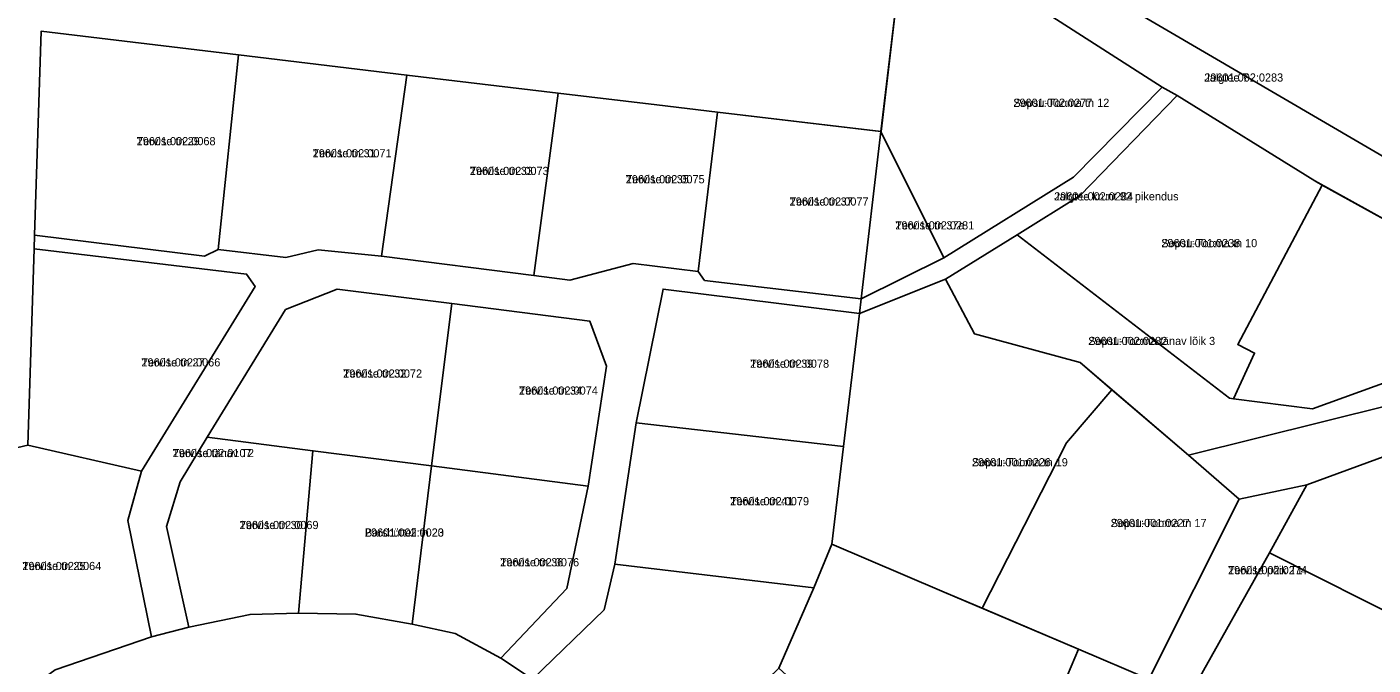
# Model space of a CAD drawing. Extents: x 518839 to 525192, y 6573164 to 6576561.
# Drawn here: x 522397.5 to 522644.9, y 6574846 to 6574963.2 of the extents above; entities that cross this region are included whole.
import ezdxf

# ---------------------------------------------------------------- set-up
doc = ezdxf.new("R2010")
doc.units = 0
for name, color, linetype in [('L_AADRESS', 7, 'Continuous'), ('PIIR', 7, 'Continuous'), ('TUNNUS', 7, 'Continuous')]:
    doc.layers.add(name, color=color, linetype=linetype)

msp = doc.modelspace()

# ---------------------------------------------------------------- linework, layer by layer
at = {"layer": 'PIIR'}
for points in [[(522594.13, 6575277.81), (522653.18, 6575274.63), (522643.43, 6575222.37), (522704.46, 6575214.76), (522708.49, 6575264.65), (522749.68, 6575255.25), (522741.36, 6575209.99), (522734.5, 6575171.21), (522773.81, 6575162.85), (522725.33, 6574926.11), (522705.01, 6574921.1), (522686, 6574922.8), (522656.89, 6574933.47), (522592.43, 6574971.18), (522560.6, 6574995.36)], [(522560.6, 6574995.36), (522592.43, 6574971.18), (522656.89, 6574933.47), (522686, 6574922.8), (522705.01, 6574921.1), (522725.33, 6574926.11), (522723.6, 6574917.68), (522697.29, 6574913.83), (522683.37, 6574910.97), (522682.62, 6574914.53), (522657.66, 6574921.95), (522634.19, 6574934.9), (522608.9, 6574950.59), (522606.14, 6574952.12), (522569.54, 6574975.64), (522558.33, 6574976.27)], [(522558.33, 6574976.27), (522569.54, 6574975.64), (522606.14, 6574952.12), (522589.83, 6574935.6), (522566.01, 6574920.76), (522554.47, 6574943.99)], [(522400.15, 6574962.4), (522436.45, 6574958.07), (522432.71, 6574922.32), (522430.18, 6574921.11), (522398.94, 6574924.94)], [(522436.45, 6574958.07), (522467.36, 6574954.37), (522462.67, 6574921.06), (522451.07, 6574922.28), (522445.13, 6574920.86), (522432.71, 6574922.32)], [(522467.36, 6574954.37), (522495.14, 6574951.05), (522490.71, 6574917.51), (522462.67, 6574921.06)], [(522495.14, 6574951.05), (522513.31, 6574948.88), (522524.42, 6574947.56), (522520.89, 6574918.25), (522508.96, 6574919.74), (522497.28, 6574916.68), (522490.71, 6574917.51)], [(522550.82, 6574913.25), (522566.01, 6574920.76), (522589.83, 6574935.6), (522606.14, 6574952.12), (522608.9, 6574950.59), (522591.05, 6574932.24), (522579.51, 6574925), (522566.31, 6574916.86), (522550.5, 6574910.54)], [(522618.51, 6574895.01), (522579.51, 6574925), (522591.05, 6574932.24), (522608.9, 6574950.59), (522634.19, 6574934.9), (522635.56, 6574934.11), (522620.02, 6574904.85), (522623.11, 6574903.27), (522619.24, 6574894.9)], [(522524.42, 6574947.56), (522554.47, 6574943.99), (522550.82, 6574913.25), (522522.07, 6574916.6), (522520.89, 6574918.25)], [(522554.47, 6574943.99), (522566.01, 6574920.76), (522550.82, 6574913.25)], [(522620.02, 6574904.85), (522635.56, 6574934.11), (522657.66, 6574921.95), (522682.62, 6574914.53), (522683.37, 6574910.97), (522633.75, 6574893.05), (522619.24, 6574894.9), (522623.11, 6574903.27)], [(522398.94, 6574924.94), (522430.18, 6574921.11), (522432.71, 6574922.32), (522445.13, 6574920.86), (522451.07, 6574922.28), (522462.67, 6574921.06), (522490.71, 6574917.51), (522497.28, 6574916.68), (522508.96, 6574919.74), (522520.89, 6574918.25), (522522.07, 6574916.6), (522550.82, 6574913.25), (522550.5, 6574910.54), (522514.43, 6574915.03), (522509.51, 6574890.48), (522505.54, 6574864.52), (522503.58, 6574856.12), (522490.42, 6574843.39), (522484.64, 6574847.21), (522496.74, 6574860.01), (522500.65, 6574878.85), (522504.03, 6574900.88), (522500.98, 6574909.12), (522475.61, 6574912.42), (522454.55, 6574915.02), (522445.07, 6574911.26), (522430.64, 6574887.81), (522425.69, 6574879.64), (522423.16, 6574871.41), (522427.3, 6574852.93), (522420.43, 6574851.14), (522416.06, 6574872.54), (522418.62, 6574881.57), (522439.47, 6574915.52), (522437.9, 6574917.81), (522398.85, 6574922.42)], [(522571.68, 6574906.81), (522566.31, 6574916.86), (522579.51, 6574925), (522618.51, 6574895.01), (522619.24, 6574894.9), (522633.75, 6574893.05), (522683.37, 6574910.97), (522697.29, 6574913.83), (522723.6, 6574917.68), (522722.5, 6574912.3), (522610.95, 6574884.51), (522591.08, 6574901.56)], [(522610.95, 6574884.51), (522722.5, 6574912.3), (522770.44, 6574924.25), (522778.15, 6574926.2), (522779.52, 6574918.94), (522842.76, 6574911.21), (522874.27, 6574905.74), (522901.66, 6574900.58), (522918.07, 6574903.61), (522923.7, 6574889.62), (522911.93, 6574886.68), (522903.89, 6574884.71), (522885.37, 6574890.16), (522824.83, 6574900.51), (522798.96, 6574904.15), (522768.16, 6574906.7), (522750.23, 6574907.13), (522721.17, 6574905.79), (522716.09, 6574905.16), (522685.54, 6574899.26), (522671.97, 6574893.44), (522632.74, 6574879.08), (522620.29, 6574876.47)], [(522398.85, 6574922.42), (522437.9, 6574917.81), (522439.47, 6574915.52), (522418.62, 6574881.57), (522397.69, 6574886.36)], [(522547.6, 6574886.14), (522550.5, 6574910.54), (522566.31, 6574916.86), (522571.68, 6574906.81), (522591.08, 6574901.56), (522596.9, 6574896.56), (522588.53, 6574886.77), (522573.06, 6574856.42), (522565.67, 6574859.57), (522545.47, 6574868.19)], [(522445.07, 6574911.26), (522454.55, 6574915.02), (522475.61, 6574912.42), (522471.87, 6574882.54), (522450.08, 6574885.33), (522430.64, 6574887.81)], [(522514.43, 6574915.03), (522550.5, 6574910.54), (522547.6, 6574886.14), (522509.51, 6574890.48)], [(522475.61, 6574912.42), (522500.98, 6574909.12), (522504.03, 6574900.88), (522500.65, 6574878.85), (522471.87, 6574882.54)], [(522588.53, 6574886.77), (522596.9, 6574896.56), (522610.95, 6574884.51), (522620.29, 6574876.47), (522603.71, 6574843.35), (522590.75, 6574848.88), (522573.06, 6574856.42)], [(522632.74, 6574879.08), (522671.97, 6574893.44), (522678.89, 6574839.89), (522625.88, 6574866.61)], [(522509.51, 6574890.48), (522547.6, 6574886.14), (522545.47, 6574868.19), (522542.16, 6574860.16), (522505.54, 6574864.52)], [(522372.96, 6574880.62), (522397.69, 6574886.36), (522418.62, 6574881.57), (522416.06, 6574872.54), (522420.43, 6574851.14), (522402.75, 6574845.12), (522387, 6574833.63), (522381.66, 6574835.01)], [(522430.64, 6574887.81), (522450.08, 6574885.33), (522447.43, 6574855.49), (522438.54, 6574855.26), (522427.3, 6574852.93), (522423.16, 6574871.41), (522425.69, 6574879.64)], [(522450.08, 6574885.33), (522471.87, 6574882.54), (522468.36, 6574853.48), (522457.99, 6574855.32), (522447.43, 6574855.49)], [(522471.87, 6574882.54), (522500.65, 6574878.85), (522496.74, 6574860.01), (522484.64, 6574847.21), (522476.2, 6574851.79), (522468.36, 6574853.48)], [(522620.29, 6574876.47), (522632.74, 6574879.08), (522625.88, 6574866.61), (522612.32, 6574842.43), (522610.9, 6574840.29), (522603.71, 6574843.35)], [(522545.47, 6574868.19), (522565.67, 6574859.57), (522590.75, 6574848.88), (522588.76, 6574844.1), (522563.41, 6574820.06), (522551.03, 6574831.44), (522535.72, 6574845.42), (522542.16, 6574860.16)], [(522625.88, 6574866.61), (522678.89, 6574839.89), (522680.32, 6574828.97), (522648.95, 6574821.16), (522637.36, 6574831.5), (522612.32, 6574842.43)], [(522505.54, 6574864.52), (522542.16, 6574860.16), (522535.72, 6574845.42), (522512.63, 6574822.97), (522501.34, 6574835.37), (522490.42, 6574843.39), (522503.58, 6574856.12)]]:
    msp.add_lwpolyline(points, close=True, dxfattribs=at)
for points in [[(522558.33, 6574976.27), (522554.49, 6574943.99), (522524.42, 6574947.56), (522513.31, 6574948.88), (522495.14, 6574951.05), (522467.36, 6574954.37), (522436.45, 6574958.07), (522400.15, 6574962.4), (522398.94, 6574924.94), (522398.85, 6574922.42), (522397.69, 6574886.36), (522372.96, 6574880.62), (522370.52, 6574880.06), (522367.6, 6574879.38), (522354.95, 6574876.44), (522349.39, 6574883.21), (522333.86, 6574902.12), (522313.55, 6574903.56), (522274.91, 6574883.71), (522271.33, 6574881.87), (522227.77, 6574859.5), (522221, 6574856.02), (522216.66, 6574846.23), (522148.05, 6574852.71)], [(522387, 6574833.63), (522402.75, 6574845.12), (522420.43, 6574851.14), (522427.3, 6574852.93), (522438.54, 6574855.26), (522447.43, 6574855.49), (522457.99, 6574855.32), (522468.36, 6574853.48), (522476.2, 6574851.79), (522484.64, 6574847.21), (522490.42, 6574843.39), (522501.34, 6574835.37), (522512.63, 6574822.97), (522528.17, 6574808.2), (522543.15, 6574793.83), (522564.85, 6574772.97), (522570.79, 6574767.49), (522581.56, 6574757.98), (522609.22, 6574733.56), (522616.78, 6574725.99), (522620.17, 6574721.68), (522628.17, 6574705.81), (522639.16, 6574678.8), (522648.72, 6574653.48)], [(522645.98, 6574784.28), (522614.06, 6574779.73), (522585.33, 6574775.4), (522579.36, 6574772.15), (522570.79, 6574767.49), (522564.85, 6574772.97), (522573.89, 6574781.61), (522584.69, 6574783.13), (522610, 6574786.68), (522610.9, 6574801.98), (522607.64, 6574815.83), (522600.65, 6574838.46), (522588.76, 6574844.1), (522590.75, 6574848.88), (522603.71, 6574843.35), (522610.9, 6574840.29), (522610.32, 6574837.29), (522617.35, 6574801.05), (522617.74, 6574794.72), (522622, 6574787.98), (522646.15, 6574791.36)]]:
    msp.add_lwpolyline(points, dxfattribs=at)

# ---------------------------------------------------------------- texts
at = {"layer": 'L_AADRESS'}
for s, p in [('Jalgtee 7', (522613.87, 6574953.16)), ('Sopsu-Tooma tn 12', (522578.8, 6574948.52)), ('Tervise tn 29', (522417.7, 6574941.47)), ('Tervise tn 31', (522450.04, 6574939.24)), ('Tervise tn 33', (522478.91, 6574936)), ('Tervise tn 35', (522507.57, 6574934.47)), ('Jalgtee krunt 92 pikendus', (522586.29, 6574931.33)), ('Tervise tn 37', (522537.68, 6574930.38)), ('Tervise tn 37a', (522557.1, 6574926)), ('Sopsu-Tooma tn 10', (522605.98, 6574922.74)), ('Sopsu-Tooma tänav lõik 3', (522592.56, 6574904.76)), ('Tervise tn 27', (522418.58, 6574900.83)), ('Tervise tn 32', (522455.65, 6574898.78)), ('Tervise tn 39', (522530.43, 6574900.59)), ('Tervise tn 34', (522487.95, 6574895.65)), ('Tervise tänav T2', (522424.32, 6574884.17)), ('Sopsu-Tooma tn 19', (522571.18, 6574882.48)), ('Tervise tn 41', (522526.75, 6574875.32)), ('Tervise tn 30', (522436.62, 6574870.95)), ('Barsbütteli tn 20', (522459.65, 6574869.57)), ('Sopsu-Tooma tn 17', (522596.68, 6574871.32)), ('Tervise tn 36', (522484.5, 6574864.1)), ('Tervise tn 25', (522396.7, 6574863.42)), ('Tervise põik T1', (522618.23, 6574862.65))]:
    msp.add_text(s, height=1.5, dxfattribs=at).set_placement(p)
at = {"layer": 'TUNNUS'}
for s, p in [('29601:002:0283', (522613.87, 6574953.16)), ('29601:002:0277', (522578.8, 6574948.52)), ('29601:002:0068', (522417.7, 6574941.47)), ('29601:002:0071', (522450.04, 6574939.24)), ('29601:002:0073', (522478.91, 6574936)), ('29601:002:0075', (522507.57, 6574934.47)), ('29601:002:0284', (522586.29, 6574931.33)), ('29601:002:0077', (522537.68, 6574930.38)), ('29601:002:0281', (522557.1, 6574926)), ('29601:001:0238', (522605.98, 6574922.74)), ('29601:002:0282', (522592.56, 6574904.76)), ('29601:002:0066', (522418.58, 6574900.83)), ('29601:002:0072', (522455.65, 6574898.78)), ('29601:002:0078', (522530.43, 6574900.59)), ('29601:002:0074', (522487.95, 6574895.65)), ('29601:002:0107', (522424.32, 6574884.17)), ('29601:001:0226', (522571.18, 6574882.48)), ('29601:002:0079', (522526.75, 6574875.32)), ('29601:002:0069', (522436.62, 6574870.95)), ('29601:002:0023', (522459.65, 6574869.57)), ('29601:001:0227', (522596.68, 6574871.32)), ('29601:002:0076', (522484.5, 6574864.1)), ('29601:002:0064', (522396.7, 6574863.42)), ('29601:002:0274', (522618.23, 6574862.65))]:
    msp.add_text(s, height=1.5, dxfattribs=at).set_placement(p)

doc.saveas('drawing.dxf')
